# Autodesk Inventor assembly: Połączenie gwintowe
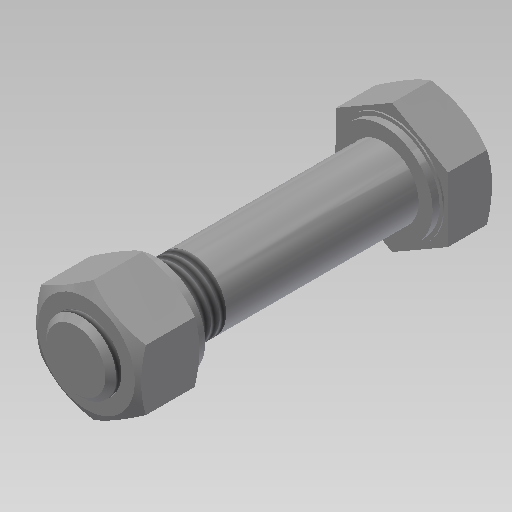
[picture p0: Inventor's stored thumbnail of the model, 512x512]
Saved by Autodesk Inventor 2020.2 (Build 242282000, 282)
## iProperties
Created: 2006-08
Part Number: Połączenie gwintowe
Document SubType Name: Assembly
Designer: F.Stasiak
ClientObjectVersion: 1
Manager: www.cadconsulting.pl
Company: Fabian Stasiak CAD Consulting
Author: F.Stasiak
Subject: Zbiór ćwiczeń. Autodesk Inventor 2020. Kurs podstawowy
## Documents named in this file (4)
- C:\2020_Kurs_podstawowy\R6 Zespoły\BOM\123-000-000\Design Accelerator\Połączenie gwintowe1.iam
- C:\2020_Kurs_podstawowy\Zasoby\Content Center Files\pl-PL\DIN 988\20-28.ipt
- C:\2020_Kurs_podstawowy\Zasoby\Content Center Files\pl-PL\DIN 6914\M20-90.ipt
- C:\2020_Kurs_podstawowy\Zasoby\Content Center Files\pl-PL\DIN EN 24 032\M20.ipt
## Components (4 placed, 3 different names)
1. DIN 988 S20 x 28:1
2. DIN 6914 M20 x 90:1
3. DIN 988 S20 x 28:2
4. DIN EN 24 032 M20:1
